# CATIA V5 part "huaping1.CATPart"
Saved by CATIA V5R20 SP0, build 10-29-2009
Part number: huaping1
Material "Dull Blue": density 7860 kg/m3, Young's modulus 2e+11 Pa, Poisson ratio 0.266
Bounding box of the stored display mesh (mm): x -33.498 to 33.498, y -33.498 to 33.464, z -1 to 120
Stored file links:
  C:\Users\12053\Desktop\huaping1.CATPart
  D:\study\catia\win_b64\startup\materials\Catalog.CATMaterial
  D:\study\catia\win_b64\startup\materials\blue_env_512x512.jpg
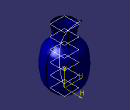
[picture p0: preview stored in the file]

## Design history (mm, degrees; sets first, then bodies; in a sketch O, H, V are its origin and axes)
Body1 (main body), material "Dull Blue"
  Plane1: type Offset, RefPlane xy-plane, Offset 20
  Plane2: type Offset, RefPlane Plane1, Offset 20
  Plane3: type Offset, RefPlane Plane2, Offset 20
  Plane4: type Offset, RefPlane Plane3, Offset 20
  Plane5: type Offset, RefPlane Plane4, Offset 20
  Sketch1 on Plane5, origin (0, 0, 100), H (1, 0, 0), V (0, 1, 0)
    circle A1 centre (0, 0) radius 17.5
    radius A1 = 17.5
  Sketch2 on Plane4, origin (0, 0, 80), H (1, 0, 0), V (0, 1, 0)
    circle A1 centre (0, 0) radius 15
    radius A1 = 15
  Sketch3 on Plane3, origin (0, 0, 60), H (1, 0, 0), V (0, 1, 0)
    circle A1 centre (0, 0) radius 30
    radius A1 = 30
  Sketch4 on Plane2, origin (0, 0, 40), H (1, 0, 0), V (0, 1, 0)
    circle A1 centre (0, 0) radius 32.5
    radius A1 = 32.5
  Sketch5 on Plane1, origin (0, 0, 20), H (1, 0, 0), V (0, 1, 0)
    circle A1 centre (0, 0) radius 30
    radius A1 = 30
  Sketch6 on xy-plane, origin (0, 0, 0), H (1, 0, 0), V (0, 1, 0)
    circle A1 centre (0, 0) radius 15
    radius A1 = 15
  Loft1: solid, Sections (Sketch1; Sketch2; Sketch3; Sketch4; Sketch5; Sketch6)
  Shell1: IntOffset 0, Face face of Loft1, ExtOffset 1
  Sketch7 on zx-plane, origin (0, 0, 0), H (-1, 0, 0), V (0, 0, 1)
  Sketch8 on yz-plane, origin (0, 0, 0), H (0, 1, 0), V (0, 0, 1)
    spline S1 through (0, 0) (-10, 40) (30, 120)
    point P1 (0, 0)
    coincidence: P1 O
